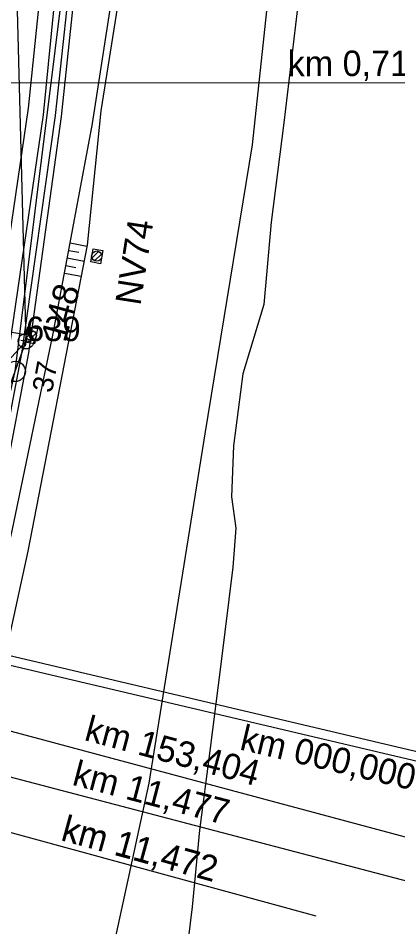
# Model space of a CAD drawing. Extents: x -598638 to -597933, y -1164002 to -1161904.
# Drawn here: x -598244.2 to -598207, y -1163425.1 to -1163336.1 of the extents above; entities that cross this region are included whole.
import ezdxf

# ---------------------------------------------------------------- set-up
doc = ezdxf.new("R2010")
doc.units = 0
for name, color, linetype in [('Vrstva 1', 7, 'Continuous'), ('Vrstva 11', 7, 'Continuous'), ('Vrstva 12', 7, 'Continuous'), ('Vrstva 31', 7, 'Continuous'), ('Vrstva 4', 7, 'Continuous'), ('Vrstva 43', 7, 'Continuous'), ('Vrstva 44', 7, 'Continuous'), ('Vrstva 48', 7, 'Continuous'), ('Vrstva 49', 7, 'Continuous'), ('Vrstva 51', 7, 'Continuous'), ('Vrstva 63', 7, 'Continuous'), ('Vrstva 7', 7, 'Continuous')]:
    doc.layers.add(name, color=color, linetype=linetype)

msp = doc.modelspace()

# ---------------------------------------------------------------- linework, layer by layer
at = {"layer": 'Vrstva 1'}
for p, q in [((-598178.553, -1163342.41), (-598275.08, -1163342.522)), ((-598174.849, -1163416.038), (-598262.877, -1163395.251)), ((-598264.28, -1163400.716), (-598191.237, -1163420.309))]:
    msp.add_line(p, q, dxfattribs=at)
for points in [[(-598254.294, -1163403.303), (-598252.648, -1163396.738), (-598249.139, -1163381.102), (-598246.501, -1163367.254), (-598243.179, -1163344.93), (-598241.198, -1163325.59), (-598240.025, -1163305.166), (-598239.731, -1163287.87)], [(-598129.944, -1163393.23), (-598184.352, -1163380.422), (-598191.576, -1163411.115), (-598252.648, -1163396.738)], [(-598192.218, -1163424.255), (-598246.5, -1163410.019), (-598245.354, -1163405.648), (-598259.151, -1163402.029)], [(-598192.218, -1163424.255), (-598246.5, -1163410.019), (-598245.354, -1163405.648), (-598254.294, -1163403.303)]]:
    msp.add_lwpolyline(points, dxfattribs=at)
at = {"layer": 'Vrstva 11'}
for p, q in [((-598236.971, -1163359.594), (-598236.325, -1163358.948)), ((-598236.711, -1163359.864), (-598236.056, -1163359.209)), ((-598243.381, -1163367.374), (-598242.735, -1163366.728)), ((-598243.121, -1163367.644), (-598242.466, -1163366.989))]:
    msp.add_line(p, q, dxfattribs=at)
msp.add_lwpolyline([(-598259.96, -1163364.2), (-598242.92, -1163367.19)], dxfattribs=at)
for centre in [(-598236.51, -1163359.41), (-598242.92, -1163367.19)]:
    msp.add_circle(centre, 0.5, dxfattribs=at)
at = {"layer": 'Vrstva 12'}
for points in [[(-598237.07, -1163359.99), (-598236.87, -1163358.7), (-598235.92, -1163358.88), (-598236.14, -1163360.17), (-598237.07, -1163359.99)], [(-598243.53, -1163367.83), (-598243.27, -1163366.34), (-598242.31, -1163366.5), (-598242.61, -1163368), (-598243.53, -1163367.83)]]:
    msp.add_lwpolyline(points, dxfattribs=at)
at = {"layer": 'Vrstva 31'}
for points in [[(-598207.807, -1163230.178), (-598207.737, -1163231.91), (-598206.446, -1163256.076), (-598207.647, -1163270.113), (-598209.267, -1163280.588), (-598205.591, -1163282.28), (-598205.96, -1163285.899), (-598206.803, -1163289.722), (-598210.416, -1163300.959), (-598213.085, -1163308.46), (-598214.501, -1163314.219), (-598215.23, -1163321.556), (-598216.701, -1163334.011), (-598218.19, -1163346.355), (-598219.432, -1163356.097), (-598220.134, -1163364.145)], [(-598220.134, -1163364.145), (-598222.214, -1163370.933), (-598223.118, -1163377.976), (-598223.32, -1163382.978), (-598222.869, -1163386.043), (-598223.176, -1163389.861), (-598224.368, -1163399.347), (-598225.435, -1163407.841), (-598226.453, -1163415.611), (-598227.155, -1163423.111), (-598228.162, -1163431.35), (-598228.664, -1163434.06), (-598229.568, -1163434.642), (-598230.959, -1163439.204), (-598232.415, -1163441.82), (-598235.521, -1163445.52), (-598237.626, -1163447.823)]]:
    msp.add_lwpolyline(points, dxfattribs=at)
at = {"layer": 'Vrstva 4'}
for points in [[(-598321.684, -1163563.952), (-598314.649, -1163552.341), (-598302.065, -1163529.781), (-598292.77, -1163512.02), (-598281.731, -1163489.572), (-598274.163, -1163472.668), (-598266.066, -1163452.17), (-598258.953, -1163431.709), (-598252.674, -1163410.241), (-598246.46, -1163386.104), (-598243.144, -1163368.884), (-598239.955, -1163345.756), (-598237.56, -1163323.253), (-598236.679, -1163305.47), (-598236.283, -1163282.744), (-598236.431, -1163244.569), (-598236.596, -1163214.625), (-598236.873, -1163174.881), (-598236.229, -1163131.239), (-598234.781, -1163108.249), (-598234.285, -1163099.455), (-598231.787, -1163078.342)], [(-598283.36, -1163489.15), (-598275.736, -1163471.917), (-598267.551, -1163451.028), (-598260.793, -1163431.262), (-598254.345, -1163409.722), (-598248.47, -1163385.636), (-598245.045, -1163368.352), (-598241.712, -1163345.6), (-598239.462, -1163322.753), (-598238.478, -1163305.467), (-598238.203, -1163283.28), (-598238.406, -1163245.16), (-598238.376, -1163215.168), (-598238.53, -1163175.26), (-598238.394, -1163131.328), (-598237.202, -1163108.683), (-598236.122, -1163097.625), (-598233.737, -1163078.205)]]:
    msp.add_lwpolyline(points, dxfattribs=at)
at = {"layer": 'Vrstva 43'}
msp.add_circle((-598244.494, -1163370.7), 1, dxfattribs=at)
at = {"layer": 'Vrstva 44'}
msp.add_lwpolyline([(-598286.823, -1163498.793), (-598268.977, -1163457.491), (-598254.684, -1163414.899), (-598244.494, -1163370.7), (-598238.629, -1163323.594), (-598237.183, -1163277.386), (-598237.387, -1163227.403), (-598237.546, -1163176.839), (-598237.218, -1163130.355), (-598233.358, -1163084.011), (-598224.142, -1163038.365), (-598215.269, -1163005.578), (-598224.817, -1163002.559)], dxfattribs=at)
at = {"layer": 'Vrstva 48'}
for p, q in [((-598237.467, -1163358.461), (-598239.117, -1163358.154)), ((-598238.267, -1163359.075), (-598239.254, -1163358.892)), ((-598237.753, -1163359.934), (-598239.391, -1163359.629)), ((-598238.549, -1163360.548), (-598239.528, -1163360.366)), ((-598238.039, -1163361.406), (-598239.665, -1163361.103))]:
    msp.add_line(p, q, dxfattribs=at)
at = {"layer": 'Vrstva 49'}
for points in [[(-598312.315, -1163561.929), (-598312.053, -1163560.13), (-598297.72, -1163533.783), (-598287.557, -1163512.375), (-598279.159, -1163492.971), (-598271.476, -1163473.929), (-598263.327, -1163452.767), (-598256.849, -1163432.711), (-598250.447, -1163410.888), (-598244.786, -1163386.292), (-598240.759, -1163366.985), (-598236.936, -1163346.431), (-598233.733, -1163325.755), (-598232.232, -1163311.779)], [(-598232.232, -1163311.779), (-598233.089, -1163326.313), (-598236.119, -1163345.209), (-598237.446, -1163358.355), (-598243.268, -1163388.291), (-598247.561, -1163407.939), (-598253.242, -1163428.023), (-598260.918, -1163451.594), (-598268.495, -1163470.375), (-598277.5, -1163493.166), (-598288.559, -1163518.332), (-598296.048, -1163535.039), (-598302.041, -1163547.928), (-598308.079, -1163558.087)], [(-598218.985, -1163327.148), (-598221.29, -1163348.513), (-598225.915, -1163376.811), (-598231.389, -1163411.005), (-598238.962, -1163445.678)]]:
    msp.add_lwpolyline(points, dxfattribs=at)
at = {"layer": 'Vrstva 51'}
msp.add_lwpolyline([(-598282.309, -1163489.477), (-598274.667, -1163472.413), (-598266.77, -1163451.853), (-598259.621, -1163431.675), (-598253.513, -1163410.04), (-598247.112, -1163385.98), (-598243.846, -1163368.944), (-598240.561, -1163345.639), (-598238.081, -1163322.667), (-598237.343, -1163305.453), (-598236.795, -1163282.909), (-598237.051, -1163244.829), (-598237.298, -1163214.833), (-598237.439, -1163175.203), (-598237.167, -1163131.222), (-598235.767, -1163108.629), (-598234.985, -1163097.818), (-598232.528, -1163078.41)], dxfattribs=at)
at = {"layer": 'Vrstva 63'}
for p, q in [((-598243.435, -1163367.735), (-598248.331, -1163175.227)), ((-598304.703, -1163434.652), (-598243.435, -1163367.735)), ((-598303.776, -1163532.286), (-598243.435, -1163367.735)), ((-598243.485, -1163367.735), (-598243.385, -1163367.735))]:
    msp.add_line(p, q, dxfattribs=at)
msp.add_circle((-598243.435, -1163367.735), 0.756, dxfattribs=at)
at = {"layer": 'Vrstva 7'}
for p, q in [((-598242.941, -1163367.81), (-598243.929, -1163367.66)), ((-598243.36, -1163367.241), (-598243.51, -1163368.229))]:
    msp.add_line(p, q, dxfattribs=at)
for points in [[(-598258.029, -1163407.473), (-598246.5, -1163410.019), (-598247.923, -1163414.996), (-598215.049, -1163423.983)], [(-598252.148, -1163408.362), (-598246.529, -1163409.898), (-598247.923, -1163414.996), (-598215.049, -1163423.983)]]:
    msp.add_lwpolyline(points, dxfattribs=at)

# ---------------------------------------------------------------- texts
at = {"layer": 'Vrstva 1'}
for s, rotation, p in [('km 0,713', 0.07016, (-598217.804, -1163341.806)), ('km 153,404', 344.98033, (-598237.826, -1163406.763)), ('km 000,000', 346.71108, (-598222.6, -1163407.685)), ('km 11,477', 345.30886, (-598239.014, -1163411.146)), ('km 11,477', 345.30886, (-598239.014, -1163411.146))]:
    msp.add_text(s, height=2.5, rotation=rotation, dxfattribs=at).set_placement(p)
at = {"layer": 'Vrstva 11'}
for s, rotation, p in [('NV74', 81.18812, (-598232.234, -1163364.317)), ('148', 74.92655, (-598239.579, -1163367.947))]:
    msp.add_text(s, height=2.5, rotation=rotation, dxfattribs=at).set_placement(p)
at = {"layer": 'Vrstva 43'}
msp.add_text('37', height=2, rotation=79.21456, dxfattribs=at).set_placement((-598240.892, -1163372.862))
at = {"layer": 'Vrstva 63'}
msp.add_text('639', height=2.4, dxfattribs=at).set_placement((-598243.435, -1163367.735))
at = {"layer": 'Vrstva 7'}
for rotation, p in [(344.71026, (-598240.123, -1163416.569)), (344.53196, (-598240.108, -1163416.513))]:
    msp.add_text('km 11,472', height=2.5, rotation=rotation, dxfattribs=at).set_placement(p)

doc.saveas('drawing.dxf')
